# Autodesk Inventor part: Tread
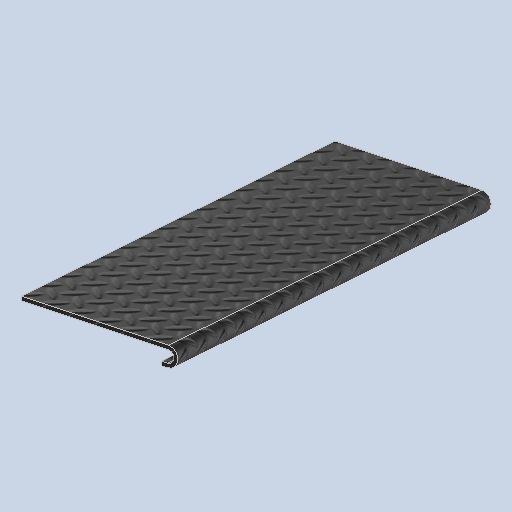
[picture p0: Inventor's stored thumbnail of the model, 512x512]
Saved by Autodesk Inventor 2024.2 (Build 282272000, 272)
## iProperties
RuleStatus: InUse
Created: 2022-06
Part Number: Tread
Material: Steel, Wrought
Document SubType Name: Modeling
Designer: reaumed
Density: 7.85 g/cm^3
Appearance: Diamond plate 2 - Dark Gray
Mass: 13075.7 g
Surface Area: 5392.46 cm^2
Volume: 1665.69 cm^3
AfterMaterialChange0: Appearance Override
Author: reaumed
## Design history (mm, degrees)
workplane "Work Plane (Rise)"
sketch "Tread Profile Sketch"
  geometry: L1 (0, 342.9)-(254, 342.9); L2 (254, 342.9)-(254, -342.9); L3 (254, -342.9)-(0, -342.9); L4 (0, -342.9)-(0, 342.9); 2 further points
  constraints: 8 end point, 2 parallel, 1 coincident, 1 horizontal, 1 midpoint, 1 perpendicular
  dimensions: "d4" = 685.8 distance of L1.end L2.end (derived); "d5" = 254 distance of L1.start L1.end (derived)
extrude "Tread Extrusion" new body sketch "Tread Profile Sketch" distance "d6" = 31.75 (derived); taper "d7" = 0 deg
fillet "Fillet1" dims "d9" = 15.875 (derived)
shell "Shell1" dims "d10" = 6.35
thicken "Thicken1" dims "d11" = 9.525 (= NosingGap), "d12" = 9.525 (= NosingGap)
body "Solid2"
other parameters: "d8" = -190.5 (derived), "StringerThickness" = 38.1 [user parameter; used in 1 equation term], "NosingGap" = 9.525 [user parameter; used in 2 equation terms]
